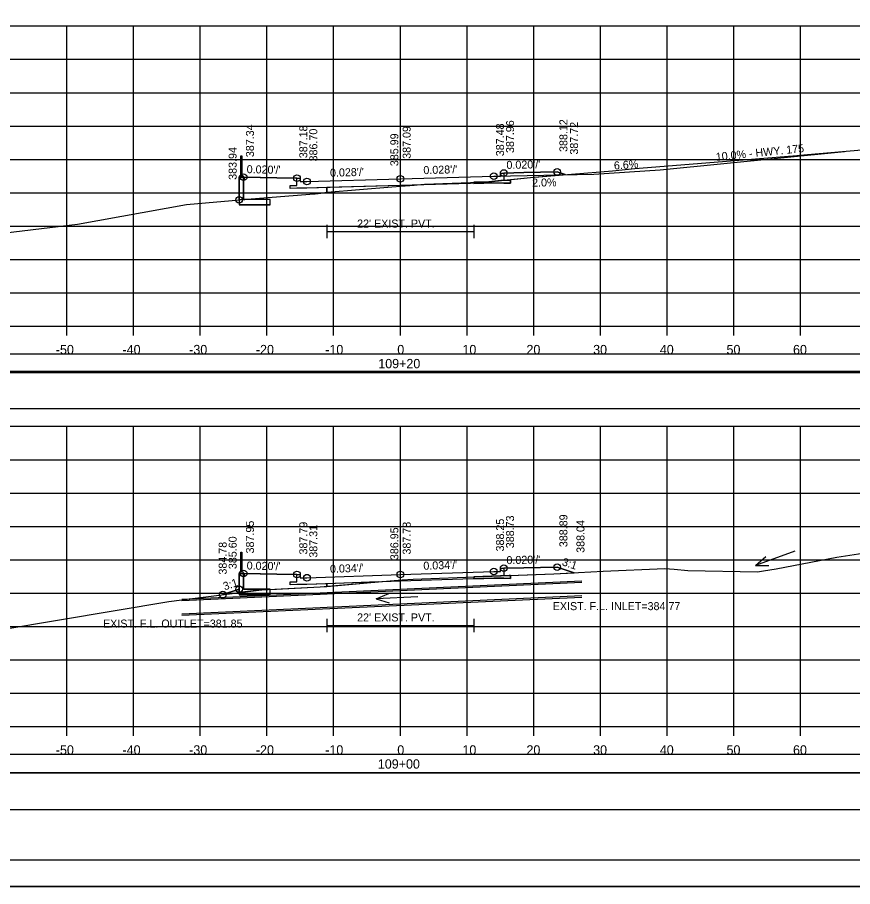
# Model space of a CAD drawing. Extents: x -37291014 to -37290680, y -936053 to -933067.
# Drawn here: x -37290900.5 to -37290775.3, y -934346.6 to -934216.3 of the extents above; entities that cross this region are included whole.
import ezdxf

# ---------------------------------------------------------------- set-up
doc = ezdxf.new("R2010")
doc.units = 0
for name, color, linetype in [('Default', 7, 'Continuous'), ('R_Alt Surface', 7, 'Continuous'), ('R_Axis', 7, 'Continuous'), ('R_Axis Annot', 7, 'Continuous'), ('R_Border', 7, 'Continuous'), ('R_Contours', 7, 'Continuous'), ('R_Drive', 7, 'Continuous'), ('R_Exist Surface', 7, 'Continuous'), ('R_Fin Surface', 7, 'Continuous'), ('R_Grid', 7, 'Continuous'), ('R_No Plot', 7, 'Continuous'), ('R_Water', 7, 'Continuous'), ('R_Water Annot', 7, 'Continuous'), ('R_Xsect Elev', 7, 'Continuous'), ('R_Xsect Slope', 7, 'Continuous')]:
    doc.layers.add(name, color=color, linetype=linetype)

msp = doc.modelspace()

# ---------------------------------------------------------------- linework, layer by layer
at = {"layer": 'Default'}
for p, q in [((-37290867.02, -934240.09), (-37290867.02, -934237.09)), ((-37290867.02, -934237.09), (-37290866.85, -934237.09)), ((-37290866.85, -934237.09), (-37290866.85, -934240.09)), ((-37290867.21, -934240.11), (-37290867.27, -934240.17)), ((-37290867.27, -934240.17), (-37290867.27, -934244.44)), ((-37290866.66, -934240.09), (-37290867.21, -934240.09)), ((-37290867.21, -934240.09), (-37290867.21, -934240.11)), ((-37290866.66, -934240.11), (-37290867.21, -934240.11)), ((-37290866.66, -934240.11), (-37290866.66, -934240.09)), ((-37290866.6, -934240.17), (-37290866.66, -934240.11)), ((-37290866.6, -934243.61), (-37290866.6, -934240.17)), ((-37290862.6, -934244.44), (-37290867.27, -934244.44)), ((-37290862.6, -934243.61), (-37290866.6, -934243.61)), ((-37290862.6, -934244.44), (-37290862.6, -934243.61)), ((-37290867.02, -934299.48), (-37290867.02, -934296.48)), ((-37290867.02, -934296.48), (-37290866.85, -934296.48)), ((-37290866.85, -934296.48), (-37290866.85, -934299.48)), ((-37290867.21, -934299.5), (-37290867.27, -934299.57)), ((-37290867.27, -934299.57), (-37290867.27, -934302.85)), ((-37290866.66, -934299.48), (-37290867.21, -934299.48)), ((-37290867.21, -934299.48), (-37290867.21, -934299.5)), ((-37290866.66, -934299.5), (-37290867.21, -934299.5)), ((-37290866.66, -934299.5), (-37290866.66, -934299.48)), ((-37290866.6, -934299.57), (-37290866.66, -934299.5)), ((-37290866.6, -934302.02), (-37290866.6, -934299.57)), ((-37290862.6, -934302.85), (-37290867.27, -934302.85)), ((-37290862.6, -934302.02), (-37290866.6, -934302.02)), ((-37290862.6, -934302.85), (-37290862.6, -934302.02))]:
    msp.add_line(p, q, dxfattribs=at)
for points in [[(-37290866.52, -934240.78), (-37290866.6, -934240.78), (-37290866.6, -934240.28), (-37290866.52, -934240.28), (-37290866.52, -934240.78)], [(-37290866.52, -934300.17), (-37290866.6, -934300.17), (-37290866.6, -934299.67), (-37290866.52, -934299.67), (-37290866.52, -934300.17)]]:
    msp.add_lwpolyline(points, dxfattribs=at)
for points in [[(-37290992.31, -934269.53), (-37290693.89, -934269.53), (-37290693.89, -934266.82), (-37290992.31, -934266.82)], [(-37290992.18, -934274.93), (-37290693.77, -934274.93), (-37290693.77, -934269.4), (-37290992.18, -934269.4)], [(-37290992.31, -934329.53), (-37290693.89, -934329.53), (-37290693.89, -934326.82), (-37290992.31, -934326.82)], [(-37290992.31, -934335.05), (-37290693.89, -934335.05), (-37290693.89, -934329.53), (-37290992.31, -934329.53)]]:
    msp.add_lwpolyline(points, close=True, dxfattribs=at)
at = {"layer": 'R_Alt Surface'}
for points in [[(-37290827.6, -934239.66), (-37290827.6, -934240.75), (-37290826.59, -934240.77), (-37290826.6, -934241.19), (-37290827.6, -934241.17), (-37290829.1, -934241.14), (-37290843.1, -934241.53), (-37290857.1, -934241.92), (-37290858.6, -934241.95), (-37290859.6, -934241.97), (-37290859.61, -934241.55), (-37290858.6, -934241.53), (-37290858.6, -934240.44)], [(-37290854.1, -934247.43), (-37290854.1, -934249.43)], [(-37290854.1, -934248.43), (-37290832.1, -934248.43)], [(-37290832.1, -934247.43), (-37290832.1, -934249.43)], [(-37290827.6, -934298.89), (-37290827.6, -934299.98), (-37290826.59, -934300), (-37290826.6, -934300.42), (-37290827.6, -934300.4), (-37290829.1, -934300.37), (-37290843.1, -934300.84), (-37290857.1, -934301.31), (-37290858.6, -934301.34), (-37290859.6, -934301.36), (-37290859.61, -934300.94), (-37290858.6, -934300.92), (-37290858.6, -934299.83)], [(-37290854.1, -934306.46), (-37290854.1, -934308.46)], [(-37290832.1, -934306.46), (-37290832.1, -934308.46)], [(-37290854.1, -934307.46), (-37290832.1, -934307.46)]]:
    msp.add_lwpolyline(points, dxfattribs=at)
at = {"layer": 'R_Axis'}
for p, q in [((-37290993.1, -934262.62), (-37290693.1, -934262.62)), ((-37290893.1, -934264.02), (-37290893.1, -934262.62)), ((-37290883.1, -934264.02), (-37290883.1, -934262.62)), ((-37290873.1, -934264.02), (-37290873.1, -934262.62)), ((-37290863.1, -934264.02), (-37290863.1, -934262.62)), ((-37290853.1, -934264.02), (-37290853.1, -934262.62)), ((-37290843.1, -934264.02), (-37290843.1, -934262.62)), ((-37290833.1, -934264.02), (-37290833.1, -934262.62)), ((-37290823.1, -934264.02), (-37290823.1, -934262.62)), ((-37290813.1, -934264.02), (-37290813.1, -934262.62)), ((-37290803.1, -934264.02), (-37290803.1, -934262.62)), ((-37290793.1, -934264.02), (-37290793.1, -934262.62)), ((-37290783.1, -934264.02), (-37290783.1, -934262.62)), ((-37290993.1, -934322.62), (-37290693.1, -934322.62)), ((-37290893.1, -934324.02), (-37290893.1, -934322.62)), ((-37290883.1, -934324.02), (-37290883.1, -934322.62)), ((-37290873.1, -934324.02), (-37290873.1, -934322.62)), ((-37290863.1, -934324.02), (-37290863.1, -934322.62)), ((-37290853.1, -934324.02), (-37290853.1, -934322.62)), ((-37290843.1, -934324.02), (-37290843.1, -934322.62)), ((-37290833.1, -934324.02), (-37290833.1, -934322.62)), ((-37290823.1, -934324.02), (-37290823.1, -934322.62)), ((-37290813.1, -934324.02), (-37290813.1, -934322.62)), ((-37290803.1, -934324.02), (-37290803.1, -934322.62)), ((-37290793.1, -934324.02), (-37290793.1, -934322.62)), ((-37290783.1, -934324.02), (-37290783.1, -934322.62))]:
    msp.add_line(p, q, dxfattribs=at)
at = {"layer": 'R_Border'}
msp.add_line((-37290684.92, -934342.62), (-37291001.1, -934342.62), dxfattribs=at)
at = {"layer": 'R_Contours'}
for p, q in [((-37290827.6, -934239.66), (-37290827.6, -934240.73)), ((-37290827.6, -934240.73), (-37290823.58, -934240.31)), ((-37290823.58, -934240.31), (-37290818.39, -934239.9)), ((-37290818.39, -934239.9), (-37290819.6, -934239.5)), ((-37290866.6, -934240.78), (-37290866.6, -934243.61)), ((-37290843.1, -934241.53), (-37290854.1, -934241.83)), ((-37290854.1, -934241.83), (-37290854.1, -934242.56)), ((-37290854.1, -934242.56), (-37290854.1, -934241.83)), ((-37290841.05, -934241.47), (-37290843.1, -934241.53)), ((-37290832.1, -934241.05), (-37290832.1, -934241.22)), ((-37290832.1, -934241.22), (-37290829.1, -934241.14)), ((-37290866.43, -934243.61), (-37290867.27, -934243.68)), ((-37290867.27, -934244.44), (-37290862.6, -934244.44)), ((-37290866.6, -934243.61), (-37290866.43, -934243.61)), ((-37290862.6, -934243.61), (-37290866.43, -934243.61)), ((-37290862.6, -934244.44), (-37290862.6, -934243.61)), ((-37290817.04, -934299.58), (-37290819.6, -934298.73)), ((-37290866.52, -934300.17), (-37290866.6, -934300.17)), ((-37290866.6, -934300.17), (-37290866.6, -934302.02)), ((-37290866.52, -934299.67), (-37290866.52, -934300.17)), ((-37290826.8, -934300), (-37290832.1, -934300.2)), ((-37290832.1, -934300.2), (-37290832.1, -934300.47)), ((-37290832.1, -934300.47), (-37290829.1, -934300.37)), ((-37290826.8, -934300), (-37290820.11, -934299.75)), ((-37290820.11, -934299.75), (-37290817.04, -934299.58)), ((-37290854.1, -934301.61), (-37290846.42, -934300.95)), ((-37290846.42, -934300.95), (-37290854.1, -934301.21)), ((-37290854.1, -934301.61), (-37290854.1, -934301.21)), ((-37290854.1, -934301.21), (-37290854.1, -934301.61)), ((-37290867.27, -934302.02), (-37290869.73, -934302.84)), ((-37290869.73, -934302.84), (-37290867.27, -934302.52)), ((-37290867.27, -934302.52), (-37290867.27, -934302.02)), ((-37290867.27, -934302.52), (-37290867.27, -934302.85)), ((-37290867.27, -934302.85), (-37290862.6, -934302.85)), ((-37290862.6, -934302.85), (-37290862.6, -934302.06))]:
    msp.add_line(p, q, dxfattribs=at)
for points in [[(-37290866.52, -934240.28), (-37290866.52, -934240.78), (-37290866.6, -934240.78)], [(-37290858.6, -934240.44), (-37290861.6, -934240.38), (-37290866.52, -934240.28)], [(-37290854.1, -934241.83), (-37290857.1, -934241.92), (-37290858.6, -934241.95), (-37290859.6, -934241.97), (-37290859.61, -934241.55), (-37290858.6, -934241.53), (-37290858.6, -934240.44)], [(-37290827.6, -934240.73), (-37290829.85, -934240.96), (-37290832.1, -934241.05)], [(-37290829.1, -934241.14), (-37290827.6, -934241.17), (-37290826.6, -934241.19), (-37290826.59, -934240.77), (-37290827.6, -934240.75), (-37290827.6, -934240.73)], [(-37290819.6, -934239.5), (-37290824.6, -934239.6), (-37290827.6, -934239.66)], [(-37290854.1, -934242.56), (-37290854.06, -934242.55), (-37290844.4, -934241.74), (-37290841.7, -934241.52), (-37290841.05, -934241.47)], [(-37290866.43, -934243.61), (-37290865.47, -934243.52), (-37290856.01, -934242.79), (-37290855.87, -934242.77), (-37290854.1, -934242.56)], [(-37290867.27, -934243.68), (-37290867.27, -934243.68), (-37290867.27, -934244.44)], [(-37290819.6, -934298.73), (-37290824.6, -934298.83), (-37290827.6, -934298.89)], [(-37290827.6, -934298.89), (-37290827.6, -934299.98), (-37290826.8, -934300)], [(-37290866.52, -934299.67), (-37290866.52, -934300.17), (-37290866.6, -934300.17), (-37290866.6, -934302.02), (-37290862.6, -934302.02), (-37290862.6, -934302.06)], [(-37290858.6, -934299.83), (-37290861.6, -934299.77), (-37290866.52, -934299.67)], [(-37290854.1, -934301.21), (-37290857.1, -934301.31), (-37290858.6, -934301.34), (-37290859.6, -934301.36), (-37290859.61, -934300.94), (-37290858.6, -934300.92), (-37290858.6, -934299.83)], [(-37290829.1, -934300.37), (-37290827.6, -934300.4), (-37290826.6, -934300.42), (-37290826.59, -934300), (-37290826.8, -934300)], [(-37290862.6, -934302.06), (-37290855.14, -934301.7), (-37290854.1, -934301.61)], [(-37290867.27, -934302.02), (-37290867.27, -934302.02)], [(-37290862.6, -934302.06), (-37290863.85, -934302.12), (-37290863.88, -934302.12), (-37290864.15, -934302.13), (-37290864.33, -934302.15), (-37290867.27, -934302.52)], [(-37290866.6, -934302.02), (-37290862.6, -934302.02), (-37290862.6, -934302.06)]]:
    msp.add_lwpolyline(points, dxfattribs=at)
at = {"layer": 'R_Drive'}
for p, q in [((-37290804.13, -934239.18), (-37290776.48, -934236.42)), ((-37290814.1, -934239.84), (-37290804.13, -934239.18)), ((-37290829.1, -934240.14), (-37290814.1, -934239.84))]:
    msp.add_line(p, q, dxfattribs=at)
at = {"layer": 'R_Exist Surface'}
for points in [[(-37290910.65, -934249.64), (-37290891.49, -934247.31), (-37290875.16, -934244.38), (-37290865.47, -934243.52), (-37290856.01, -934242.79), (-37290855.87, -934242.77), (-37290854.06, -934242.55), (-37290844.4, -934241.74), (-37290841.7, -934241.52), (-37290839.47, -934241.35), (-37290829.85, -934240.96), (-37290823.58, -934240.31), (-37290811.3, -934239.35), (-37290807.94, -934238.99), (-37290797.28, -934238.13), (-37290783.64, -934237.03), (-37290783.35, -934237.01), (-37290783.22, -934236.99), (-37290772.75, -934236.1)], [(-37290910.94, -934309.42), (-37290877.81, -934303.86), (-37290875.88, -934303.63), (-37290864.33, -934302.15), (-37290864.15, -934302.13), (-37290863.88, -934302.12), (-37290863.85, -934302.12), (-37290855.14, -934301.7), (-37290844.03, -934300.75), (-37290842.85, -934300.64), (-37290841.19, -934300.54), (-37290820.11, -934299.75), (-37290812.68, -934299.34), (-37290803.43, -934298.94), (-37290802.06, -934299.01), (-37290799.97, -934299.22), (-37290789.56, -934299.45), (-37290788.67, -934299.28), (-37290786.76, -934298.96), (-37290777.66, -934297.24), (-37290765.94, -934295.45)]]:
    msp.add_lwpolyline(points, dxfattribs=at)
at = {"layer": 'R_Fin Surface'}
for p, q in [((-37290819.6, -934239.5), (-37290818.39, -934239.9)), ((-37290819.6, -934298.73), (-37290817.04, -934299.58))]:
    msp.add_line(p, q, dxfattribs=at)
for points in [[(-37290867.27, -934243.68), (-37290867.27, -934240.28), (-37290866.6, -934240.28), (-37290861.6, -934240.38), (-37290858.6, -934240.44), (-37290858.1, -934240.44), (-37290858.1, -934240.94), (-37290857.1, -934240.92), (-37290843.1, -934240.53), (-37290829.1, -934240.14), (-37290828.1, -934240.16), (-37290828.1, -934239.66), (-37290827.6, -934239.66), (-37290824.6, -934239.6), (-37290819.6, -934239.5)], [(-37290869.73, -934302.84), (-37290867.27, -934302.02), (-37290867.27, -934299.67), (-37290866.6, -934299.67), (-37290861.6, -934299.77), (-37290858.6, -934299.83), (-37290858.1, -934299.83), (-37290858.1, -934300.33), (-37290857.1, -934300.31), (-37290843.1, -934299.84), (-37290829.1, -934299.37), (-37290828.1, -934299.39), (-37290828.1, -934298.89), (-37290827.6, -934298.89), (-37290824.6, -934298.83), (-37290819.6, -934298.73)]]:
    msp.add_lwpolyline(points, dxfattribs=at)
at = {"layer": 'R_Grid'}
for p, q in [((-37290993.1, -934217.62), (-37290693.1, -934217.62)), ((-37290893.1, -934262.62), (-37290893.1, -934217.62)), ((-37290883.1, -934262.62), (-37290883.1, -934217.62)), ((-37290873.1, -934262.62), (-37290873.1, -934217.62)), ((-37290863.1, -934262.62), (-37290863.1, -934217.62)), ((-37290853.1, -934262.62), (-37290853.1, -934217.62)), ((-37290843.1, -934262.62), (-37290843.1, -934217.62)), ((-37290833.1, -934262.62), (-37290833.1, -934217.62)), ((-37290823.1, -934262.62), (-37290823.1, -934217.62)), ((-37290813.1, -934262.62), (-37290813.1, -934217.62)), ((-37290803.1, -934262.62), (-37290803.1, -934217.62)), ((-37290793.1, -934262.62), (-37290793.1, -934217.62)), ((-37290783.1, -934262.62), (-37290783.1, -934217.62)), ((-37290993.1, -934222.62), (-37290693.1, -934222.62)), ((-37290993.1, -934227.62), (-37290693.1, -934227.62)), ((-37290993.1, -934232.62), (-37290693.1, -934232.62)), ((-37290993.1, -934237.62), (-37290693.1, -934237.62)), ((-37290993.1, -934242.62), (-37290693.1, -934242.62)), ((-37290993.1, -934247.62), (-37290693.1, -934247.62)), ((-37290993.1, -934252.62), (-37290693.1, -934252.62)), ((-37290993.1, -934257.62), (-37290693.1, -934257.62)), ((-37290993.1, -934262.62), (-37290693.1, -934262.62)), ((-37290993.1, -934277.62), (-37290693.1, -934277.62)), ((-37290893.1, -934322.62), (-37290893.1, -934277.62)), ((-37290883.1, -934322.62), (-37290883.1, -934277.62)), ((-37290873.1, -934322.62), (-37290873.1, -934277.62)), ((-37290863.1, -934322.62), (-37290863.1, -934277.62)), ((-37290853.1, -934322.62), (-37290853.1, -934277.62)), ((-37290843.1, -934322.62), (-37290843.1, -934277.62)), ((-37290833.1, -934322.62), (-37290833.1, -934277.62)), ((-37290823.1, -934322.62), (-37290823.1, -934277.62)), ((-37290813.1, -934322.62), (-37290813.1, -934277.62)), ((-37290803.1, -934322.62), (-37290803.1, -934277.62)), ((-37290793.1, -934322.62), (-37290793.1, -934277.62)), ((-37290783.1, -934322.62), (-37290783.1, -934277.62)), ((-37290993.1, -934282.62), (-37290693.1, -934282.62)), ((-37290993.1, -934287.62), (-37290693.1, -934287.62)), ((-37290993.1, -934292.62), (-37290693.1, -934292.62)), ((-37290993.1, -934297.62), (-37290693.1, -934297.62)), ((-37290993.1, -934302.62), (-37290693.1, -934302.62)), ((-37290993.1, -934307.62), (-37290693.1, -934307.62)), ((-37290993.1, -934312.62), (-37290693.1, -934312.62)), ((-37290993.1, -934317.62), (-37290693.1, -934317.62)), ((-37290993.1, -934322.62), (-37290693.1, -934322.62))]:
    msp.add_line(p, q, dxfattribs=at)
at = {"layer": 'R_No Plot'}
for p, q in [((-37290815.9, -934300.83), (-37290875.85, -934303.57)), ((-37290815.9, -934303.25), (-37290875.85, -934305.98)), ((-37291013.5, -934346.6), (-37290680.17, -934346.6))]:
    msp.add_line(p, q, dxfattribs=at)
for points in [[(-37291013.51, -934133.27), (-37290680.17, -934133.27), (-37290680.17, -934346.6), (-37291013.51, -934346.6)], [(-37290767.18, -934137.16), (-37290747.56, -934137.16), (-37290747.56, -934147.04), (-37290731.45, -934147.04), (-37290708.25, -934147.04), (-37290708.25, -934171.37), (-37290684.92, -934171.37), (-37290684.92, -934342.62), (-37291001.1, -934342.62), (-37291001.1, -934137.16)]]:
    msp.add_lwpolyline(points, close=True, dxfattribs=at)
for centre in [(-37290827.6, -934239.66), (-37290819.6, -934239.5), (-37290866.6, -934240.28), (-37290858.6, -934240.44), (-37290857.1, -934240.92), (-37290843.1, -934240.53), (-37290829.1, -934240.14), (-37290829.1, -934240.14), (-37290867.27, -934243.68), (-37290866.6, -934299.67), (-37290858.6, -934299.83), (-37290843.1, -934299.84), (-37290829.1, -934299.37), (-37290829.1, -934299.37), (-37290827.6, -934298.89), (-37290819.6, -934298.73), (-37290857.1, -934300.31), (-37290867.27, -934302.02), (-37290869.73, -934302.84)]:
    msp.add_circle(centre, 0.5, dxfattribs=at)
at = {"layer": 'R_Water'}
for p, q in [((-37290815.9, -934301.04), (-37290875.85, -934303.77)), ((-37290815.9, -934303.04), (-37290875.85, -934305.77))]:
    msp.add_line(p, q, dxfattribs=at)
at = {"layer": 'R_Water Annot'}
for p, q in [((-37290783.96, -934296.33), (-37290789.87, -934298.46)), ((-37290789.87, -934298.46), (-37290788.3, -934297.15)), ((-37290789.87, -934298.46), (-37290787.83, -934298.47)), ((-37290846.74, -934303.46), (-37290844.85, -934302.67)), ((-37290840.46, -934303.17), (-37290846.74, -934303.46)), ((-37290846.74, -934303.46), (-37290844.78, -934304.07))]:
    msp.add_line(p, q, dxfattribs=at)
at = {"layer": 'R_Xsect Elev'}
for p, q in [((-37290843.1, -934241.63), (-37290843.1, -934231.63)), ((-37290843.1, -934300.67), (-37290843.1, -934290.67))]:
    msp.add_line(p, q, dxfattribs=at)

# ---------------------------------------------------------------- texts
at = {"layer": 'R_Axis Annot'}
for s, p in [('-50', (-37290894.76, -934266.82)), ('-40', (-37290884.76, -934266.82)), ('-30', (-37290874.76, -934266.82)), ('-20', (-37290864.76, -934266.82)), ('-10', (-37290854.36, -934266.82)), ('0', (-37290843.56, -934266.82)), ('10', (-37290833.79, -934266.82)), ('20', (-37290824.19, -934266.82)), ('30', (-37290814.19, -934266.82)), ('40', (-37290804.19, -934266.82)), ('50', (-37290794.19, -934266.82)), ('60', (-37290784.22, -934266.82)), ('109+20', (-37290846.41, -934268.92)), ('-50', (-37290894.76, -934326.82)), ('-40', (-37290884.76, -934326.82)), ('-30', (-37290874.76, -934326.82)), ('-20', (-37290864.76, -934326.82)), ('-10', (-37290854.36, -934326.82)), ('0', (-37290843.56, -934326.82)), ('10', (-37290833.79, -934326.82)), ('20', (-37290824.19, -934326.82)), ('30', (-37290814.19, -934326.82)), ('40', (-37290804.19, -934326.82)), ('50', (-37290794.19, -934326.82)), ('60', (-37290784.22, -934326.82)), ('109+00', (-37290846.47, -934328.92))]:
    msp.add_text(s, height=1.4, dxfattribs=at).set_placement(p)
at = {"layer": 'R_Water'}
for p in [(-37290849.58, -934247.83), (-37290849.58, -934306.86)]:
    msp.add_text("22' EXIST. PVT.", height=1.2, dxfattribs=at).set_placement(p)
at = {"layer": 'R_Water Annot'}
for s, p in [('EXIST. F.L. INLET=384.77', (-37290820.25, -934305.17)), ('EXIST. F.L. OUTLET=381.85', (-37290887.68, -934307.78))]:
    msp.add_text(s, height=1.2, dxfattribs=at).set_placement(p)
at = {"layer": 'R_Xsect Elev'}
for s, rotation, p in [('387.34', 90, (-37290865.05, -934237.28)), ('387.18', 90, (-37290857.05, -934237.44)), ('387.09', 90, (-37290841.55, -934237.53)), ('387.48', 90, (-37290827.55, -934237.14)), ('387.96', 90, (-37290826.05, -934236.66)), ('388.12', 90, (-37290818.05, -934236.5)), ('387.72', 90, (-37290816.46, -934236.9)), ('386.70', 90, (-37290855.55, -934237.92)), ('385.99', 90, (-37290843.4, -934238.63)), ('10.0% - HWY. 175', 5.7106, (-37290795.74, -934237.84)), ('383.94', 90, (-37290867.65, -934240.68)), ('6.6%', 3.776, (-37290811.04, -934239.14)), ('2.0%', 1.1458, (-37290823.33, -934241.71)), ('388.25', 90, (-37290827.55, -934296.37)), ('388.73', 90, (-37290826.05, -934295.89)), ('388.89', 90, (-37290818.05, -934295.73)), ('387.95', 90, (-37290865.05, -934296.67)), ('387.79', 90, (-37290857.05, -934296.83)), ('387.31', 90, (-37290855.55, -934297.31)), ('386.95', 90, (-37290843.4, -934297.67)), ('387.78', 90, (-37290841.55, -934296.84)), ('388.04', 90, (-37290815.49, -934296.58)), ('384.78', 90, (-37290869.14, -934299.84)), ('385.60', 90, (-37290867.65, -934299.02))]:
    msp.add_text(s, height=1.2, rotation=rotation, dxfattribs=at).set_placement(p)
at = {"layer": 'R_Xsect Slope'}
for s, rotation, p in [("0.020'/'", 1.1458, (-37290827.18, -934239.05)), ("0.020'/'", 358.8542, (-37290866.15, -934239.68)), ("0.028'/'", 1.5862, (-37290853.63, -934240.22)), ("0.028'/'", 1.5862, (-37290839.63, -934239.83)), ("0.020'/'", 358.8542, (-37290866.15, -934299.08)), ("0.034'/'", 1.9244, (-37290839.63, -934299.12)), ("0.020'/'", 1.1458, (-37290827.18, -934298.28)), ('3:1', 341.5668, (-37290818.95, -934298.42)), ("0.034'/'", 1.9244, (-37290853.63, -934299.59)), ('3:1', 18.4332, (-37290869.45, -934302.22))]:
    msp.add_text(s, height=1.2, rotation=rotation, dxfattribs=at).set_placement(p)

doc.saveas('drawing.dxf')
